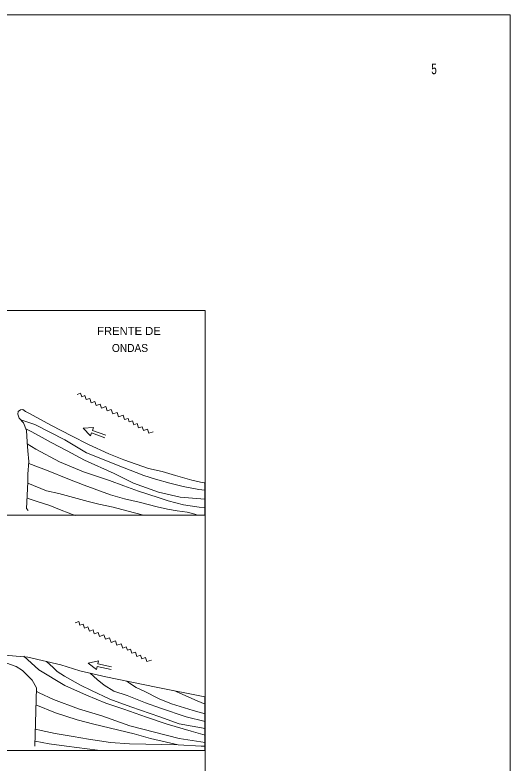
# Model space of a CAD drawing. Extents: x -175 to 1110, y -14 to 1804.
# Drawn here: x 497 to 1110, y 878 to 1804 of the extents above; entities that cross this region are included whole.
import ezdxf

# ---------------------------------------------------------------- set-up
doc = ezdxf.new("R2010")
doc.units = 0
doc.header["$LTSCALE"] = 4
doc.layers.add('1', color=7, linetype='Continuous', lineweight=13)

msp = doc.modelspace()

# ---------------------------------------------------------------- linework, layer by layer
at = {"layer": '1'}
for p, q in [((197.04, 1185.26), (732.24, 1185.26)), ((731.79, 893.88), (197.3, 893.88)), ((521.7, 893.88), (731.79, 893.88))]:
    msp.add_line(p, q, dxfattribs=at)
for points in [[(1110.15, -13.5), (1110.15, 1804.14), (-175.05, 1804.14), (-175.05, -13.5)], [(197.04, 517.8), (732.71, 517.8), (732.71, 1438.42), (197.04, 1438.42)]]:
    msp.add_lwpolyline(points, close=True, dxfattribs=at)
for points in [[(574, 1334.56), (578.31, 1336.02), (579.75, 1331.78), (583.65, 1333.11), (585.35, 1328.14), (589.66, 1329.61), (591.48, 1324.23), (595.93, 1325.75), (597.52, 1321.04), (602.36, 1322.68), (604.07, 1317.72), (609.42, 1319.54), (611.21, 1314.3), (616.3, 1316.04), (618.21, 1310.41), (623.58, 1312.24), (625.4, 1306.87), (630.9, 1308.74), (632.72, 1303.37)], [(731.58, 1225.37), (726.82, 1226.13), (716.18, 1228.42), (695.85, 1234.43), (679.17, 1239.14), (662.49, 1242.75), (631.91, 1253.79), (613.42, 1261.08), (588.16, 1272.63), (566.95, 1283.23), (542.07, 1296.25), (514.09, 1311.3), (509.89, 1313.53), (506.6, 1315.75), (503.66, 1315.59), (500.89, 1313.6), (500.49, 1310.11), (502.29, 1305.34), (507.76, 1299.25), (511.37, 1289.88), (512.17, 1275.77), (512.82, 1264.77), (514.37, 1251.38), (512.97, 1236), (512.89, 1226.1), (511.36, 1193.51), (513.54, 1190.74)], [(504.25, 1303.16), (521.52, 1297.31), (558.83, 1278.53), (585.52, 1262.38), (630.37, 1244.45), (656.73, 1234.36), (671.03, 1229.86), (688.98, 1224.58), (705.48, 1220.8), (724.54, 1216.99), (732.24, 1215.95)], [(632.72, 1303.37), (637.02, 1304.82), (638.47, 1300.58), (642.37, 1301.91), (644.06, 1296.94), (648.38, 1298.41), (650.2, 1293.05), (654.65, 1294.56), (656.24, 1289.84), (661.09, 1291.49), (662.78, 1286.52), (668.15, 1288.35)], [(732.24, 1204.97), (701.52, 1207.64), (674.94, 1213.7), (643.99, 1224.75), (619.84, 1236.65), (583.25, 1253.42), (561.66, 1264.76), (541.73, 1275.17), (526.92, 1283.53), (517.04, 1288.74), (511.92, 1291.35), (510.57, 1291.92)], [(609.5, 1284.17), (593.1, 1290.14), (594.44, 1293.84), (581.28, 1292.64)], [(608.34, 1280.99), (591.93, 1286.96), (590.59, 1283.26), (581.28, 1292.64)], [(512.3, 1273.46), (522.75, 1266.7), (552.19, 1251.09), (582.03, 1238.77), (613.89, 1228.08), (631.66, 1221.36), (649.97, 1214.81), (674.34, 1206.93), (686.79, 1202.8), (705.85, 1198.08), (724.93, 1195.18), (732.24, 1194.14)], [(514.17, 1249.27), (537.97, 1240.21), (562.32, 1230.13), (582.64, 1222.09), (615.24, 1210.49), (632.64, 1205.22), (650.79, 1201.43), (673.15, 1195.58), (685.98, 1192.72), (698.08, 1190.63), (710.19, 1188.88), (721.55, 1186.05)], [(512.82, 1224.61), (536.13, 1215.48), (551.16, 1212.07), (569.49, 1206.99), (587.81, 1202.08), (600.83, 1198.87), (618.61, 1194.88), (635.46, 1190.55), (655.99, 1185.08)], [(518.99, 1185.26), (732.24, 1185.26), (732.24, 1224.72), (731.58, 1225.37)], [(511.94, 1206.12), (525.74, 1201.82), (540.02, 1196.94), (554.3, 1191.17), (571.7, 1184.8)], [(571.74, 1051.92), (576.06, 1053.39), (577.5, 1049.15), (581.4, 1050.47), (583.09, 1045.5), (587.4, 1046.98), (589.22, 1041.6), (593.67, 1043.12), (595.27, 1038.4), (600.11, 1040.05), (601.81, 1035.08), (607.16, 1036.91), (608.96, 1031.67), (614.04, 1033.41), (615.96, 1027.77), (621.32, 1029.6), (623.15, 1024.24), (628.64, 1026.11), (630.46, 1020.73)], [(630.46, 1020.73), (634.77, 1022.18), (636.21, 1017.94), (640.11, 1019.28), (641.81, 1014.31), (646.12, 1015.78), (647.95, 1010.41), (652.4, 1011.92), (653.99, 1007.21), (658.83, 1008.85), (660.52, 1003.89), (665.89, 1005.71)], [(732.19, 960.49), (671.92, 972.41), (609.39, 984.98), (577.32, 992.56), (553.69, 1000.05), (512.81, 1009.53), (488.96, 1011.54), (442.52, 1013.72), (430.57, 1012.54), (428.17, 1010.72), (427.41, 1008.53), (428.67, 1005.41), (432.72, 1005)], [(507.86, 1010.66), (526.65, 993.67), (558.63, 974.56), (585.72, 962.25), (609.69, 952.36), (631.68, 945.04), (660.06, 935.31), (685.52, 926.68), (715.2, 918.04), (729.49, 913.71), (732.36, 912.92)], [(432.72, 1005), (446.85, 1004.9), (486.86, 1002.02), (498.41, 997.91), (506.25, 993.09), (518.1, 980.9), (523.53, 971.52), (521.7, 899.15)], [(732.36, 921.07), (700.4, 927.12), (676.22, 935.55), (640.33, 948.1), (614.33, 957.64), (591.64, 968.26), (578.1, 974.95), (558.54, 985.91), (549.4, 991.66), (544.12, 996.65), (535.91, 1004.17)], [(616.72, 997.55), (599.65, 1001.18), (600.47, 1005.03), (587.6, 1002.01)], [(616.02, 994.24), (598.94, 997.86), (598.13, 994.01), (587.6, 1002.01)], [(732.36, 929.93), (708.91, 935.49), (677.41, 946.17), (658.73, 953.09), (636.03, 962.05), (619.37, 967.5), (607.49, 974.74), (598.9, 981.76), (590.01, 989.56)], [(732.36, 939.28), (717.6, 943.48), (691.04, 951.56), (675.48, 957.9), (657, 967.21), (647.3, 972.04), (638.9, 977.24), (635.69, 979.69)], [(732.36, 903.79), (700.26, 908.98), (639.23, 924.47), (604.62, 936.83), (575.49, 945.66), (544.73, 957.25), (527.17, 965.45), (523.43, 967.29)], [(693.95, 968.06), (722.47, 955.36), (732.36, 951.48)], [(732.24, 893.88), (732.24, 960.73), (732.19, 960.49)], [(523, 950.54), (547.18, 940.74), (574.1, 932.11), (594.62, 926.64), (644.66, 914.53), (665, 908.7), (699.1, 900.93), (727.73, 899.24), (732.36, 899.12)], [(699.1, 900.93), (638.69, 902.12), (615.38, 903.94), (588.06, 907.81), (569.17, 911.44), (546.79, 915.08), (529.38, 918.89), (522.24, 920.34)], [(521.86, 905.7), (539.35, 902.32), (560.99, 899.22), (599.13, 894.33)]]:
    msp.add_lwpolyline(points, dxfattribs=at)

# ---------------------------------------------------------------- texts
for s, height, width, p in [('5', 13, 0.7, (1012.66, 1730.87)), ('FRENTE DE', 9.9, 1.05, (598.79, 1408.18)), ('ONDAS', 9.9, 0.95, (617.09, 1387.08))]:
    msp.add_text(s, height=height, dxfattribs=dict(at, width=width)).set_placement(p)

doc.saveas('drawing.dxf')
